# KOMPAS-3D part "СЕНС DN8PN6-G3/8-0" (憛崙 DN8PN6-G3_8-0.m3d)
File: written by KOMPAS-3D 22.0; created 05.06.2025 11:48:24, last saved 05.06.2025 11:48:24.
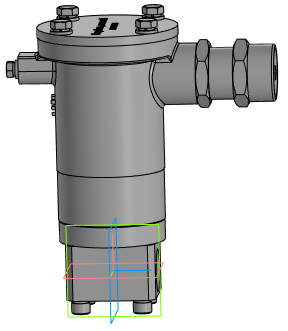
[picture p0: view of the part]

Document properties: Автор: setup; Полное имя файла: СЕНС DN8PN6-G3_8-0\СЕНС DN8PN6-G3_8-0.a3d

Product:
- Part/product: СЕНС DN8PN6-G3/8-0
    Масса: 2.061193

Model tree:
1. Операция без истории:1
